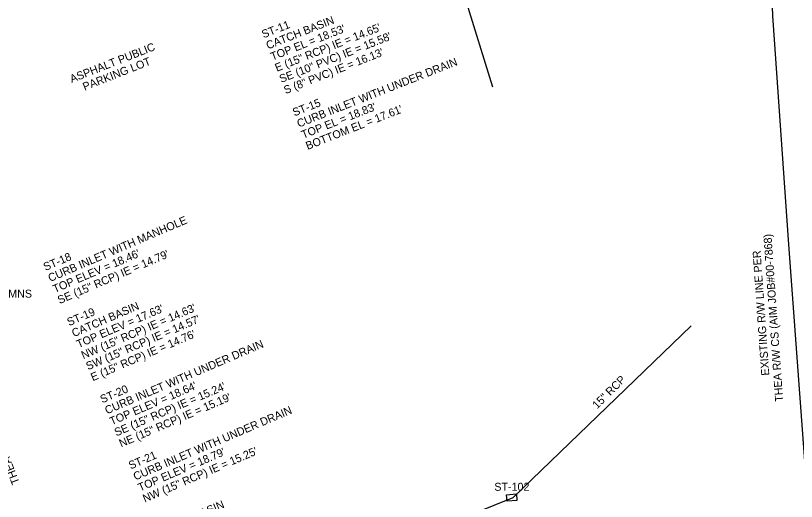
# Model space of a CAD drawing. Extents: x 509744 to 512285, y 1314862 to 1316822.
# Drawn here: x 510729.8 to 511002.9, y 1315227.8 to 1315397.8 of the extents above; entities that cross this region are included whole.
import ezdxf

# ---------------------------------------------------------------- set-up
doc = ezdxf.new("R2010")
doc.units = 0
for name, color, linetype in [('CatchBasin_ep', 7, 'Continuous'), ('LARWLine_ep', 7, 'Continuous'), ('NonPlottingEle_dp', 7, 'Continuous'), ('PipeCulvert_ep', 7, 'Continuous'), ('RWLine_ep', 7, 'Continuous'), ('TextNotes', 7, 'Continuous'), ('TextTopoLabel_ep', 7, 'Continuous')]:
    doc.layers.add(name, color=color, linetype=linetype)

msp = doc.modelspace()

# ---------------------------------------------------------------- linework, layer by layer
at = {"layer": 'CatchBasin_ep'}
msp.add_lwpolyline([(510901.52, 1315230.11), (510904.93, 1315230.39), (510905.12, 1315228.07), (510901.71, 1315227.79)], close=True, dxfattribs=at)
at = {"layer": 'LARWLine_ep'}
msp.add_line((510881.53, 1315421.39), (510896.6, 1315372.89), dxfattribs=at)
at = {"layer": 'PipeCulvert_ep'}
for p, q in [((510903.76, 1315229.17), (510966.08, 1315289.25)), ((510741.95, 1315163.72), (510903.76, 1315229.17))]:
    msp.add_line(p, q, dxfattribs=at)
at = {"layer": 'RWLine_ep'}
for p, q in [((510993.02, 1315446.78), (510994.47, 1315397.68)), ((510994.47, 1315397.68), (511000.11, 1315317.72)), ((511000.11, 1315317.72), (511010.27, 1315179.16))]:
    msp.add_line(p, q, dxfattribs=at)

# ---------------------------------------------------------------- texts
at = {"layer": 'NonPlottingEle_dp'}
for s, rotation, p in [('CATCH BASIN', 21.5246, (510818.05, 1315385.94)), ('ST-11', 21.5246, (510816.5, 1315389.85)), ("TOP EL = 18.53'", 21.5246, (510819.59, 1315382.04)), ('E (15" RCP) IE = 14.65\'', 21.5246, (510821.13, 1315378.13)), ('SE (10" PVC) IE = 15.58\'', 21.5246, (510822.67, 1315374.22)), ('S (8" PVC) IE = 16.13\'', 21.5246, (510824.21, 1315370.31)), ('CURB INLET WITH UNDER DRAIN', 21.5246, (510828.83, 1315358.59)), ('ST-15', 21.5246, (510827.29, 1315362.5)), ("TOP EL = 18.83'", 21.5246, (510830.37, 1315354.69)), ("BOTTOM EL = 17.61'", 21.5246, (510831.91, 1315350.78)), ('CURB INLET WITH MANHOLE', 23.2147, (510741.85, 1315304.53)), ('ST-18 ', 23.2147, (510740.19, 1315308.39)), ("TOP ELEV = 18.46'", 23.2147, (510743.5, 1315300.67)), ('SE (15" RCP) IE = 14.79\'', 23.2147, (510745.16, 1315296.81)), ('CATCH BASIN', 23.2147, (510750.12, 1315285.23)), ("TOP ELEV = 17.63'", 23.2147, (510751.78, 1315281.37)), ('NW (15" RCP) IE = 14.63\'', 23.2147, (510753.44, 1315277.51)), ('ST-19', 23.2147, (510748.47, 1315289.09)), ('SW (15" RCP) IE = 14.57\'', 23.2147, (510755.09, 1315273.65)), ('E (15" RCP) IE = 14.76\' ', 23.2147, (510756.75, 1315269.79)), ('CURB INLET WITH UNDER DRAIN', 23.2147, (510761.71, 1315258.21)), ('15" RCP', 45, (510933.17, 1315259.93)), ('ST-20', 23.2147, (510760.06, 1315262.07)), ("TOP ELEV = 18.64'", 23.2147, (510763.37, 1315254.35)), ('SE (15" RCP) IE = 15.24\'', 23.2147, (510765.02, 1315250.49)), ('NE (15" RCP) IE = 15.19\'', 23.2147, (510766.68, 1315246.63)), ('CURB INLET WITH UNDER DRAIN', 23.2147, (510771.65, 1315235.05)), ("TOP ELEV = 18.79'", 23.2147, (510773.3, 1315231.19)), ('NW (15" RCP) IE = 15.25\'', 23.2147, (510774.96, 1315227.33)), ('ST-21', 23.2147, (510769.99, 1315238.91)), ('CATCH BASIN', 23.2147, (510779.92, 1315215.75))]:
    msp.add_text(s, height=2.8, rotation=rotation, dxfattribs=at).set_placement(p)
msp.add_text('ST-102', height=2.8, dxfattribs=at).set_placement((510897.2, 1315231.48))
at = {"layer": 'TextNotes'}
for s, rotation, p in [('THEA R/W CS (AIM JOB#00-7868)', 94.0425, (510998.26, 1315262.73)), ('EXISTING R/W LINE PER', 94.0425, (510993.41, 1315271.89)), ('THEA SEC. 10002-2520-010', 111.1462, (510731.21, 1315234.31))]:
    msp.add_text(s, height=2.8, rotation=rotation, dxfattribs=at).set_placement(p)
at = {"layer": 'TextTopoLabel_ep'}
for s, p in [('ASPHALT PUBLIC ', (510749.4, 1315374.23)), ('PARKING LOT', (510753.9, 1315371.49))]:
    msp.add_text(s, height=2.8, rotation=21.5246, dxfattribs=at).set_placement(p)
msp.add_text("5' CONCRETE COLUMNS", height=2.8, dxfattribs=at).set_placement((510690.89, 1315299.08))

doc.saveas('drawing.dxf')
